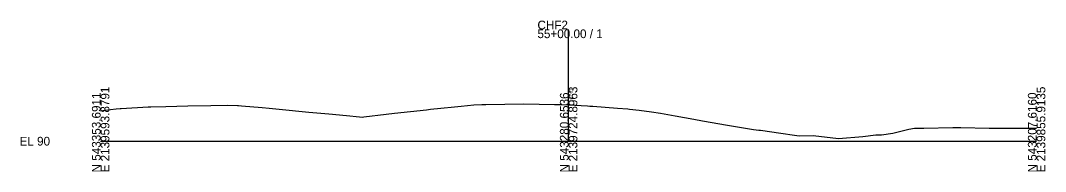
# Model space of a CAD drawing. Extents: x -12831 to 2303, y -10 to 39065.
# Drawn here: x 1974.3 to 2302.8, y 9990.3 to 10038.6 of the extents above; entities that cross this region are included whole.
import ezdxf

# ---------------------------------------------------------------- set-up
doc = ezdxf.new("R2010")
doc.units = 0
for name, color, linetype in [('RD_GPK_XS_Cell', 7, 'Continuous'), ('RD_XS_ExGround', 7, 'Continuous'), ('RD_XS_TX_Elev_EX', 7, 'Continuous')]:
    doc.layers.add(name, color=color, linetype=linetype)

msp = doc.modelspace()

# ---------------------------------------------------------------- linework, layer by layer
at = {"layer": 'RD_GPK_XS_Cell'}
for p, q in [((2150, 10000), (2150, 10035.81)), ((2000, 10000), (2150, 10000)), ((2150, 10000), (2300, 10000))]:
    msp.add_line(p, q, dxfattribs=at)
at = {"layer": 'RD_XS_ExGround'}
for p, q in [((2005.02, 10010.34), (2006.24, 10010.45)), ((2006.24, 10010.45), (2006.55, 10010.5)), ((2006.55, 10010.5), (2015.22, 10010.98)), ((2015.22, 10010.98), (2016.06, 10011.03)), ((2016.06, 10011.03), (2020.91, 10011.15)), ((2020.91, 10011.15), (2027.9, 10011.3)), ((2027.9, 10011.3), (2035.32, 10011.46)), ((2035.32, 10011.46), (2040.8, 10011.57)), ((2040.8, 10011.57), (2043.85, 10011.43)), ((2043.85, 10011.43), (2044.17, 10011.41)), ((2044.17, 10011.41), (2045.18, 10011.34)), ((2045.18, 10011.34), (2051.78, 10010.77)), ((2051.78, 10010.77), (2053.98, 10010.55)), ((2053.98, 10010.55), (2060.41, 10009.91)), ((2105.77, 10010.22), (2109.01, 10010.55)), ((2109.01, 10010.55), (2113.41, 10010.99)), ((2113.41, 10010.99), (2115.6, 10011.21)), ((2115.6, 10011.21), (2119.57, 10011.63)), ((2119.57, 10011.63), (2122.14, 10011.78)), ((2122.14, 10011.78), (2123.5, 10011.79)), ((2123.5, 10011.79), (2135.62, 10011.94)), ((2135.62, 10011.94), (2145.49, 10011.78)), ((2145.49, 10011.78), (2147.58, 10011.75)), ((2147.58, 10011.75), (2150, 10011.61)), ((2150, 10011.61), (2156.06, 10011.28)), ((2156.06, 10011.28), (2156.84, 10011.23)), ((2156.84, 10011.23), (2157.77, 10011.23)), ((2157.77, 10011.23), (2165.7, 10010.58)), ((2165.7, 10010.58), (2168.95, 10010.36)), ((2000, 10009.77), (2001.38, 10009.97)), ((2001.38, 10009.97), (2005.02, 10010.34)), ((2060.41, 10009.91), (2061.52, 10009.82)), ((2061.52, 10009.82), (2062.45, 10009.74)), ((2062.45, 10009.74), (2066.7, 10009.32)), ((2066.7, 10009.32), (2073.18, 10008.73)), ((2073.18, 10008.73), (2078.75, 10008.21)), ((2078.75, 10008.21), (2082.95, 10007.82)), ((2082.95, 10007.82), (2083.79, 10007.75)), ((2083.79, 10007.75), (2084.35, 10007.81)), ((2084.35, 10007.81), (2091.56, 10008.63)), ((2091.56, 10008.63), (2094.16, 10008.97)), ((2094.16, 10008.97), (2104.45, 10010.07)), ((2104.45, 10010.07), (2105.77, 10010.22)), ((2168.95, 10010.36), (2169.55, 10010.29)), ((2169.55, 10010.29), (2172.62, 10009.96)), ((2172.62, 10009.96), (2176.51, 10009.43)), ((2176.51, 10009.43), (2179.48, 10009.02)), ((2179.48, 10009.02), (2184.09, 10008.17)), ((2184.09, 10008.17), (2190.1, 10007.05)), ((2190.1, 10007.05), (2192.95, 10006.52)), ((2192.95, 10006.52), (2200.91, 10005.12)), ((2200.91, 10005.12), (2207.94, 10003.99)), ((2207.94, 10003.99), (2209.23, 10003.77)), ((2259.04, 10003.81), (2260.82, 10004.15)), ((2260.82, 10004.15), (2263.83, 10004.19)), ((2263.83, 10004.19), (2273.1, 10004.4)), ((2273.1, 10004.4), (2275.69, 10004.43)), ((2275.69, 10004.43), (2284.75, 10004.21)), ((2284.75, 10004.21), (2286.34, 10004.18)), ((2286.34, 10004.18), (2287.78, 10004.17)), ((2287.78, 10004.17), (2296.64, 10004.13)), ((2296.64, 10004.13), (2300, 10004.15)), ((2209.23, 10003.77), (2210.94, 10003.54)), ((2210.94, 10003.54), (2211.46, 10003.53)), ((2211.46, 10003.53), (2218, 10002.58)), ((2218, 10002.58), (2222.42, 10001.93)), ((2222.42, 10001.93), (2223.9, 10001.75)), ((2223.9, 10001.75), (2228.36, 10001.8)), ((2228.36, 10001.8), (2236.5, 10000.82)), ((2236.5, 10000.82), (2244.34, 10001.54)), ((2244.34, 10001.54), (2248.43, 10002.02)), ((2248.43, 10002.02), (2250.26, 10002.06)), ((2250.26, 10002.06), (2253.96, 10002.62)), ((2253.96, 10002.62), (2259.04, 10003.81))]:
    msp.add_line(p, q, dxfattribs=at)

# ---------------------------------------------------------------- texts
at = {"layer": 'RD_GPK_XS_Cell'}
for s, p in [('CHF2', (2140, 10035.81)), ('55+00.00 / 1', (2140, 10033.01)), ('EL 90', (1974, 9998.6))]:
    msp.add_text(s, height=2.8, dxfattribs=at).set_placement(p)
for s, p in [('E 2139593.8791', (2002.8, 9990)), ('E 2139724.8963', (2152.8, 9990)), ('E 2139855.9135', (2302.8, 9990)), ('N 543353.6911', (2000, 9990)), ('N 543280.6536', (2150, 9990)), ('N 543207.6160', (2300, 9990))]:
    msp.add_text(s, height=2.8, rotation=90, dxfattribs=at).set_placement(p)
at = {"layer": 'RD_XS_TX_Elev_EX'}
msp.add_text('101.61', height=1, rotation=90, dxfattribs=at).set_placement((2151.25, 10012.61))

doc.saveas('drawing.dxf')
